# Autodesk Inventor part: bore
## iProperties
Created: 2002-08
Part Number: bore
Document SubType Name: Modeling
Designer: t_munrn
Density: 1 g/cm^3
Control State: 0
Master: False
Checked Out: False
Shininess: 64.0
Length Units: 11269
Angle Units: 11279
Time Units: 11290
Mass Units: 11283
Length Display Precision: 3
Angle Display Precision: 2
Density: 0.0
Volumn: 0.0
Area: 0.0
PropertySet Name: Model Information
Author: t_munrn
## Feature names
1. Extrusion1
2. Extrusion2
3. Fillet1
4. Fillet2
5. Fillet3
6. Hole2
7. Circular Pattern1
